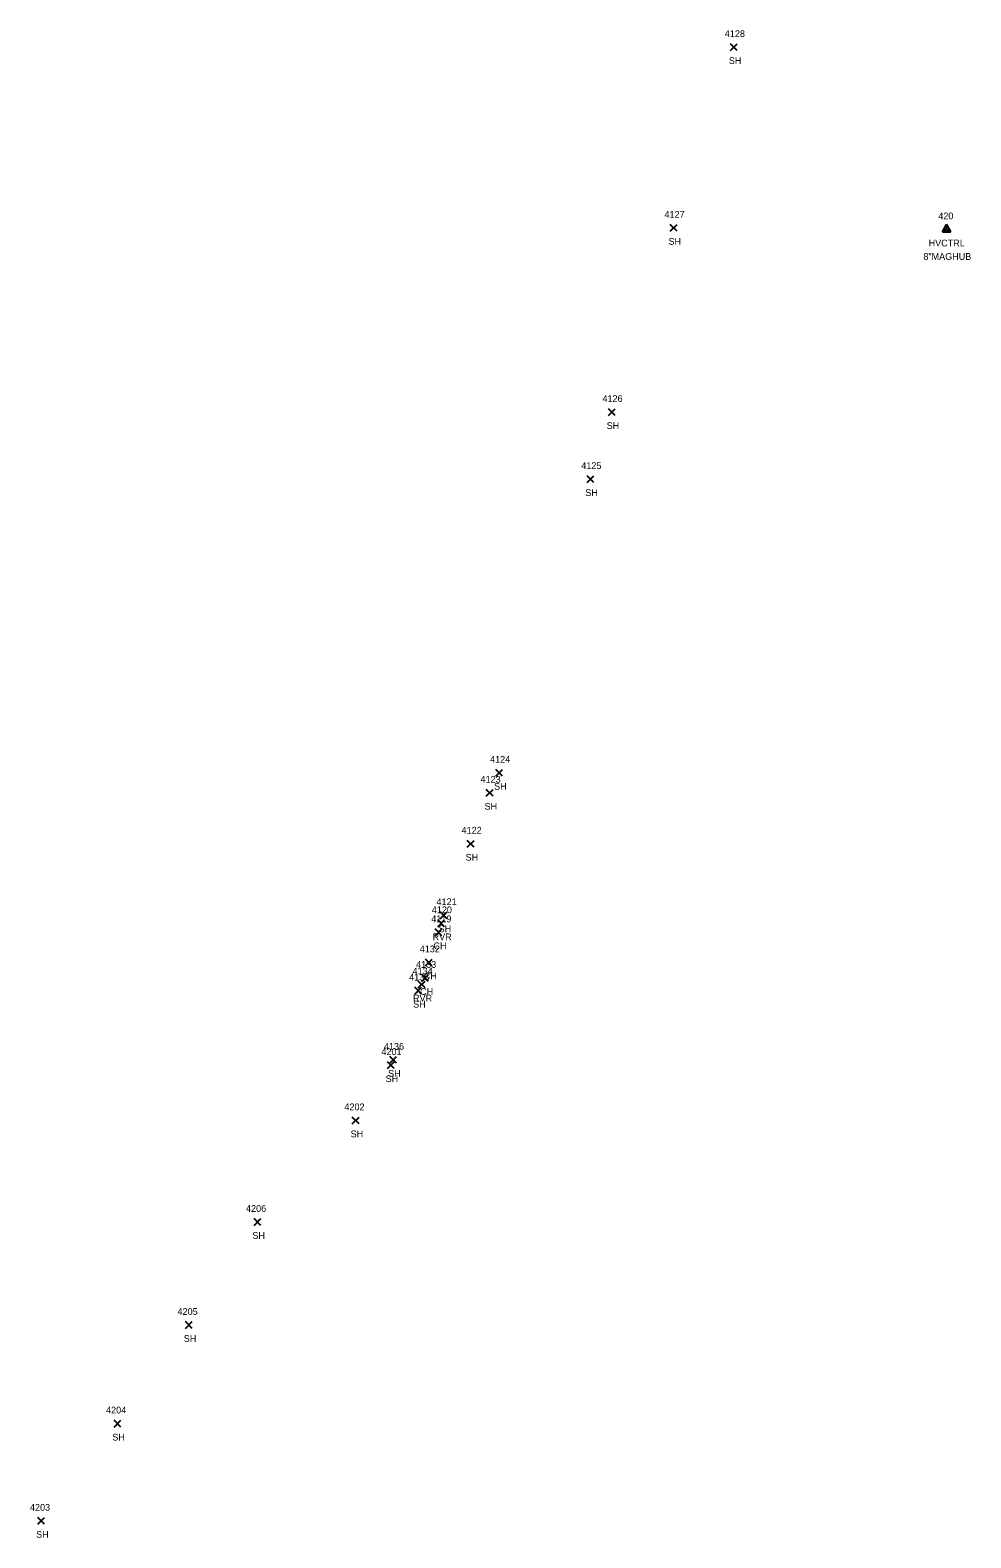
# Model space of a CAD drawing. Extents: x 1601151 to 1602912, y 499508 to 501770.
# Drawn here: x 1602577.1 to 1602855.2, y 499508.3 to 499954.4 of the extents above; entities that cross this region are included whole.
import ezdxf

# ---------------------------------------------------------------- set-up
doc = ezdxf.new("R2010")
doc.units = 0
for name, color, linetype in [('C_A', 7, 'Continuous'), ('C_C', 7, 'Continuous'), ('C_I', 7, 'Continuous'), ('CPSM', 7, 'Continuous'), ('L_A', 7, 'Continuous'), ('L_I', 7, 'Continuous'), ('L_TIC', 7, 'Continuous')]:
    doc.layers.add(name, color=color, linetype=linetype)

msp = doc.modelspace()

# ---------------------------------------------------------------- linework, layer by layer
at = {"layer": 'CPSM'}
for p, q in [((1602846.81, 499894.7), (1602848.06, 499896.87)), ((1602846.81, 499894.7), (1602848.06, 499895.42)), ((1602846.81, 499894.7), (1602849.31, 499894.7)), ((1602849.31, 499894.7), (1602848.06, 499896.87)), ((1602848.06, 499895.42), (1602848.06, 499896.87)), ((1602848.06, 499895.42), (1602848.06, 499895.42)), ((1602848.06, 499895.42), (1602849.31, 499894.7))]:
    msp.add_line(p, q, dxfattribs=at)
at = {"layer": 'L_TIC'}
for points in [[(1602784.19, 499948.37), (1602786.19, 499950.37)], [(1602786.19, 499948.37), (1602784.19, 499950.37)], [(1602766.36, 499894.89), (1602768.36, 499896.89)], [(1602768.36, 499894.89), (1602766.36, 499896.89)], [(1602748.07, 499840.38), (1602750.07, 499842.38)], [(1602750.07, 499840.38), (1602748.07, 499842.38)], [(1602741.75, 499820.54), (1602743.75, 499822.54)], [(1602743.75, 499820.54), (1602741.75, 499822.54)], [(1602714.78, 499733.65), (1602716.78, 499735.65)], [(1602716.78, 499733.65), (1602714.78, 499735.65)], [(1602711.96, 499727.72), (1602713.96, 499729.72)], [(1602713.96, 499727.72), (1602711.96, 499729.72)], [(1602706.36, 499712.65), (1602708.36, 499714.65)], [(1602708.36, 499712.65), (1602706.36, 499714.65)], [(1602698.38, 499691.48), (1602700.38, 499693.48)], [(1602700.38, 499691.48), (1602698.38, 499693.48)], [(1602696.86, 499686.44), (1602698.86, 499688.44)], [(1602698.86, 499686.44), (1602696.86, 499688.44)], [(1602697.64, 499689.1), (1602699.64, 499691.1)], [(1602699.64, 499689.1), (1602697.64, 499691.1)], [(1602694, 499677.52), (1602696, 499679.52)], [(1602696, 499677.52), (1602694, 499679.52)], [(1602692.9, 499672.93), (1602694.9, 499674.93)], [(1602694.9, 499672.93), (1602692.9, 499674.93)], [(1602690.86, 499669.18), (1602692.86, 499671.18)], [(1602692.86, 499669.18), (1602690.86, 499671.18)], [(1602691.86, 499670.98), (1602693.86, 499672.98)], [(1602693.86, 499670.98), (1602691.86, 499672.98)], [(1602682.73, 499647.12), (1602684.73, 499649.12)], [(1602684.73, 499647.12), (1602682.73, 499649.12)], [(1602683.45, 499648.68), (1602685.45, 499650.68)], [(1602685.45, 499648.68), (1602683.45, 499650.68)], [(1602672.36, 499630.79), (1602674.36, 499632.79)], [(1602674.36, 499630.79), (1602672.36, 499632.79)], [(1602643.32, 499600.73), (1602645.32, 499602.73)], [(1602645.32, 499600.73), (1602643.32, 499602.73)], [(1602623.03, 499570.24), (1602625.03, 499572.24)], [(1602625.03, 499570.24), (1602623.03, 499572.24)], [(1602601.9, 499541.06), (1602603.9, 499543.06)], [(1602603.9, 499541.06), (1602601.9, 499543.06)], [(1602579.39, 499512.29), (1602581.39, 499514.29)], [(1602581.39, 499512.29), (1602579.39, 499514.29)]]:
    msp.add_lwpolyline(points, dxfattribs=at)

# ---------------------------------------------------------------- texts
at = {"layer": 'C_A'}
msp.add_text('HVCTRL', height=2, dxfattribs=at).set_placement((1602842.75, 499890.42))
at = {"layer": 'C_C'}
msp.add_text('8"MAGHUB', height=2, dxfattribs=at).set_placement((1602841.2, 499886.42))
at = {"layer": 'C_I'}
msp.add_text('420', height=2, dxfattribs=at).set_placement((1602845.61, 499898.42))
at = {"layer": 'L_A'}
for s, p in [('SH', (1602783.68, 499944.37)), ('SH', (1602765.85, 499890.89)), ('SH', (1602747.56, 499836.38)), ('SH', (1602741.24, 499816.54)), ('SH', (1602714.27, 499729.65)), ('SH', (1602711.45, 499723.72)), ('SH', (1602705.85, 499708.65)), ('SH', (1602697.87, 499687.48)), ('RVR', (1602696.1, 499685.1)), ('CH', (1602696.35, 499682.44)), ('CH', (1602693.49, 499673.52)), ('CH', (1602692.39, 499668.93)), ('SH', (1602690.35, 499665.18)), ('RVR', (1602690.31, 499666.98)), ('SH', (1602682.22, 499643.12)), ('SH', (1602682.94, 499644.68)), ('SH', (1602671.85, 499626.79)), ('SH', (1602642.81, 499596.73)), ('SH', (1602622.52, 499566.24)), ('SH', (1602601.39, 499537.06)), ('SH', (1602578.88, 499508.29))]:
    msp.add_text(s, height=2, dxfattribs=at).set_placement(p)
at = {"layer": 'L_I'}
for s, p in [('4128', (1602782.5, 499952.37)), ('4127', (1602764.67, 499898.89)), ('4126', (1602746.32, 499844.38)), ('4125', (1602740.06, 499824.54)), ('4124', (1602713.09, 499737.65)), ('4123', (1602710.27, 499731.72)), ('4122', (1602704.67, 499716.65)), ('4121', (1602697.25, 499695.48)), ('4119', (1602695.72, 499690.44)), ('4120', (1602695.86, 499693.1)), ('4132', (1602692.31, 499681.52)), ('4133', (1602691.21, 499676.93)), ('4135', (1602689.16, 499673.18)), ('4134', (1602690.17, 499674.98)), ('4201', (1602680.96, 499651.12)), ('4136', (1602681.71, 499652.68)), ('4202', (1602670.02, 499634.79)), ('4206', (1602640.93, 499604.73)), ('4205', (1602620.69, 499574.24)), ('4204', (1602599.56, 499545.06)), ('4203', (1602577.06, 499516.29))]:
    msp.add_text(s, height=2, dxfattribs=at).set_placement(p)

doc.saveas('drawing.dxf')
